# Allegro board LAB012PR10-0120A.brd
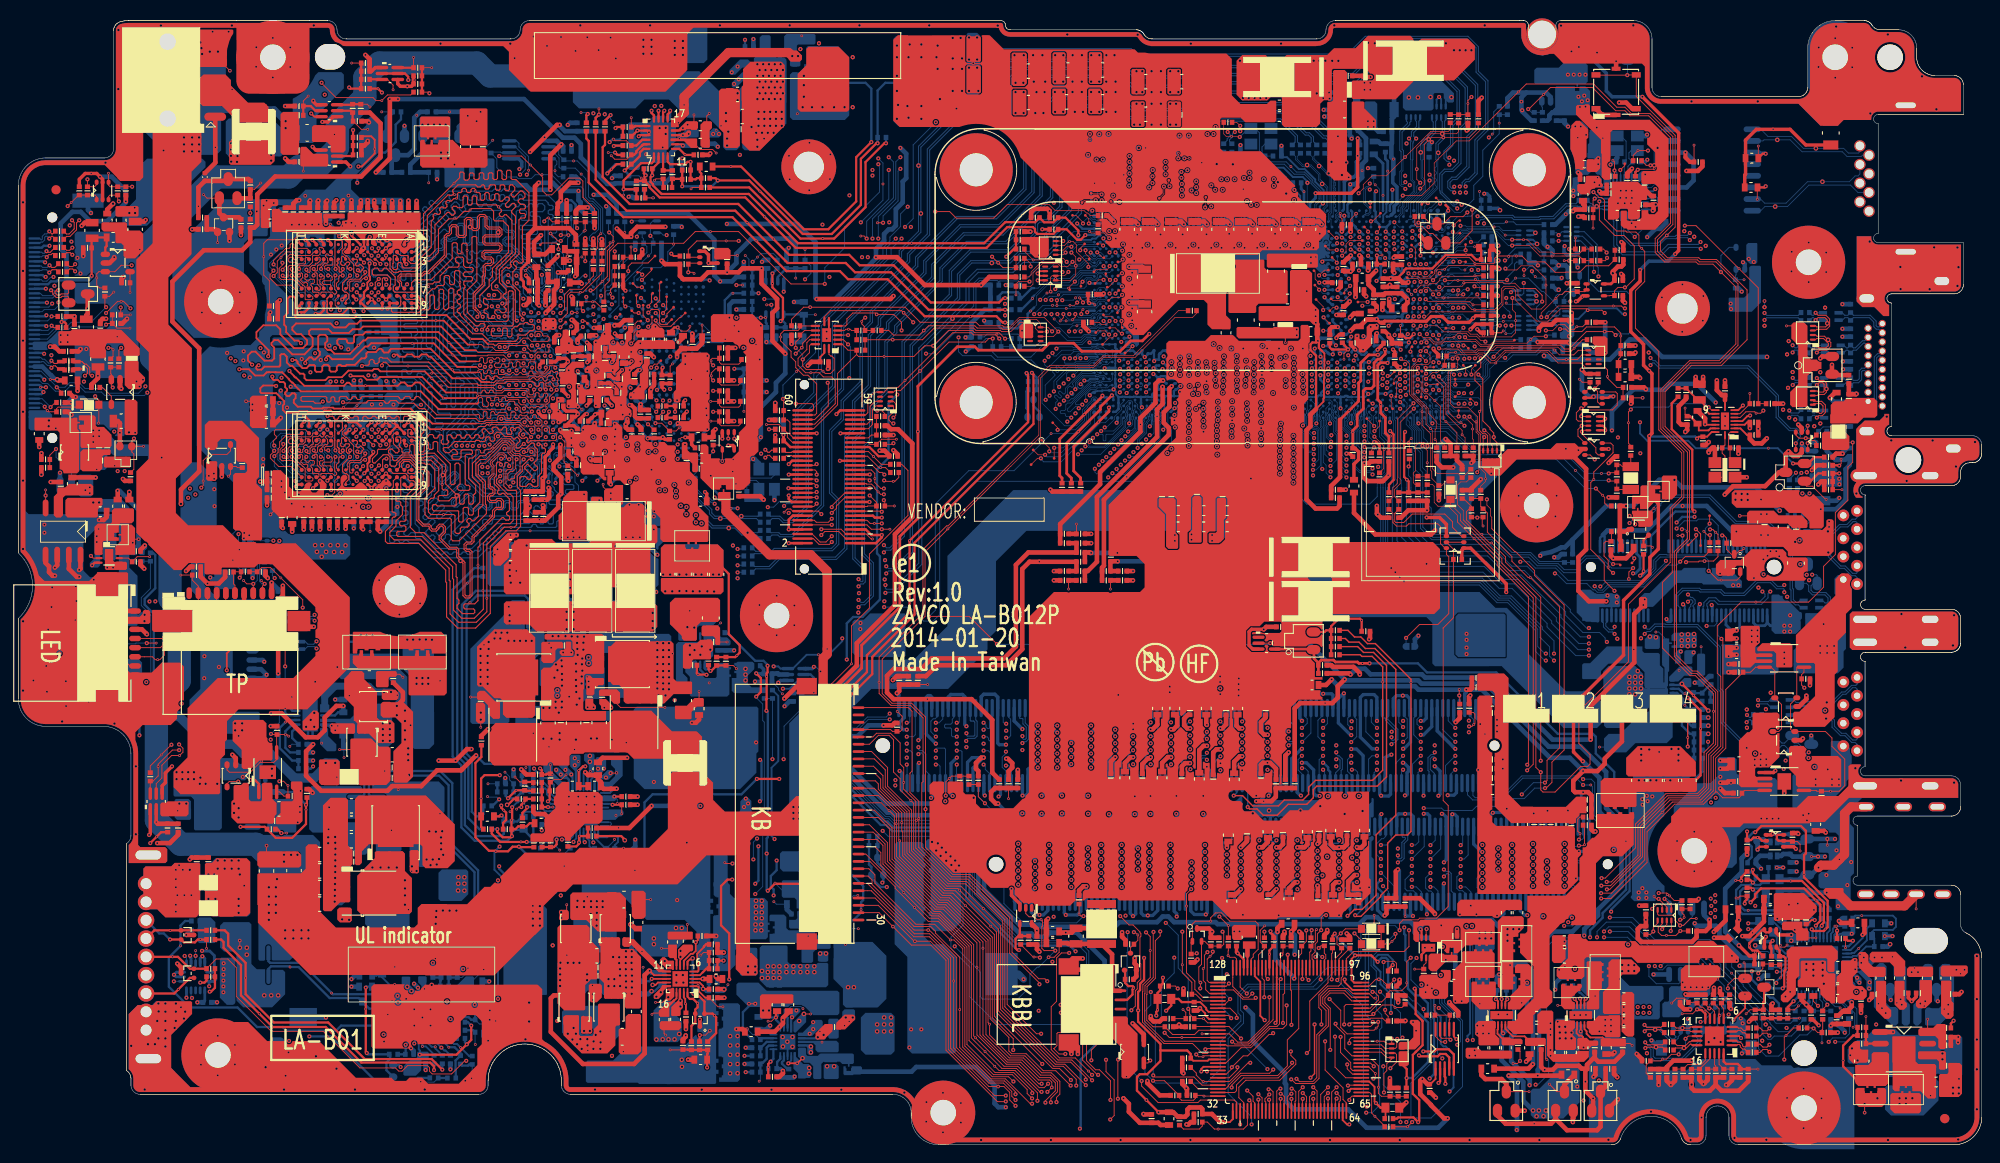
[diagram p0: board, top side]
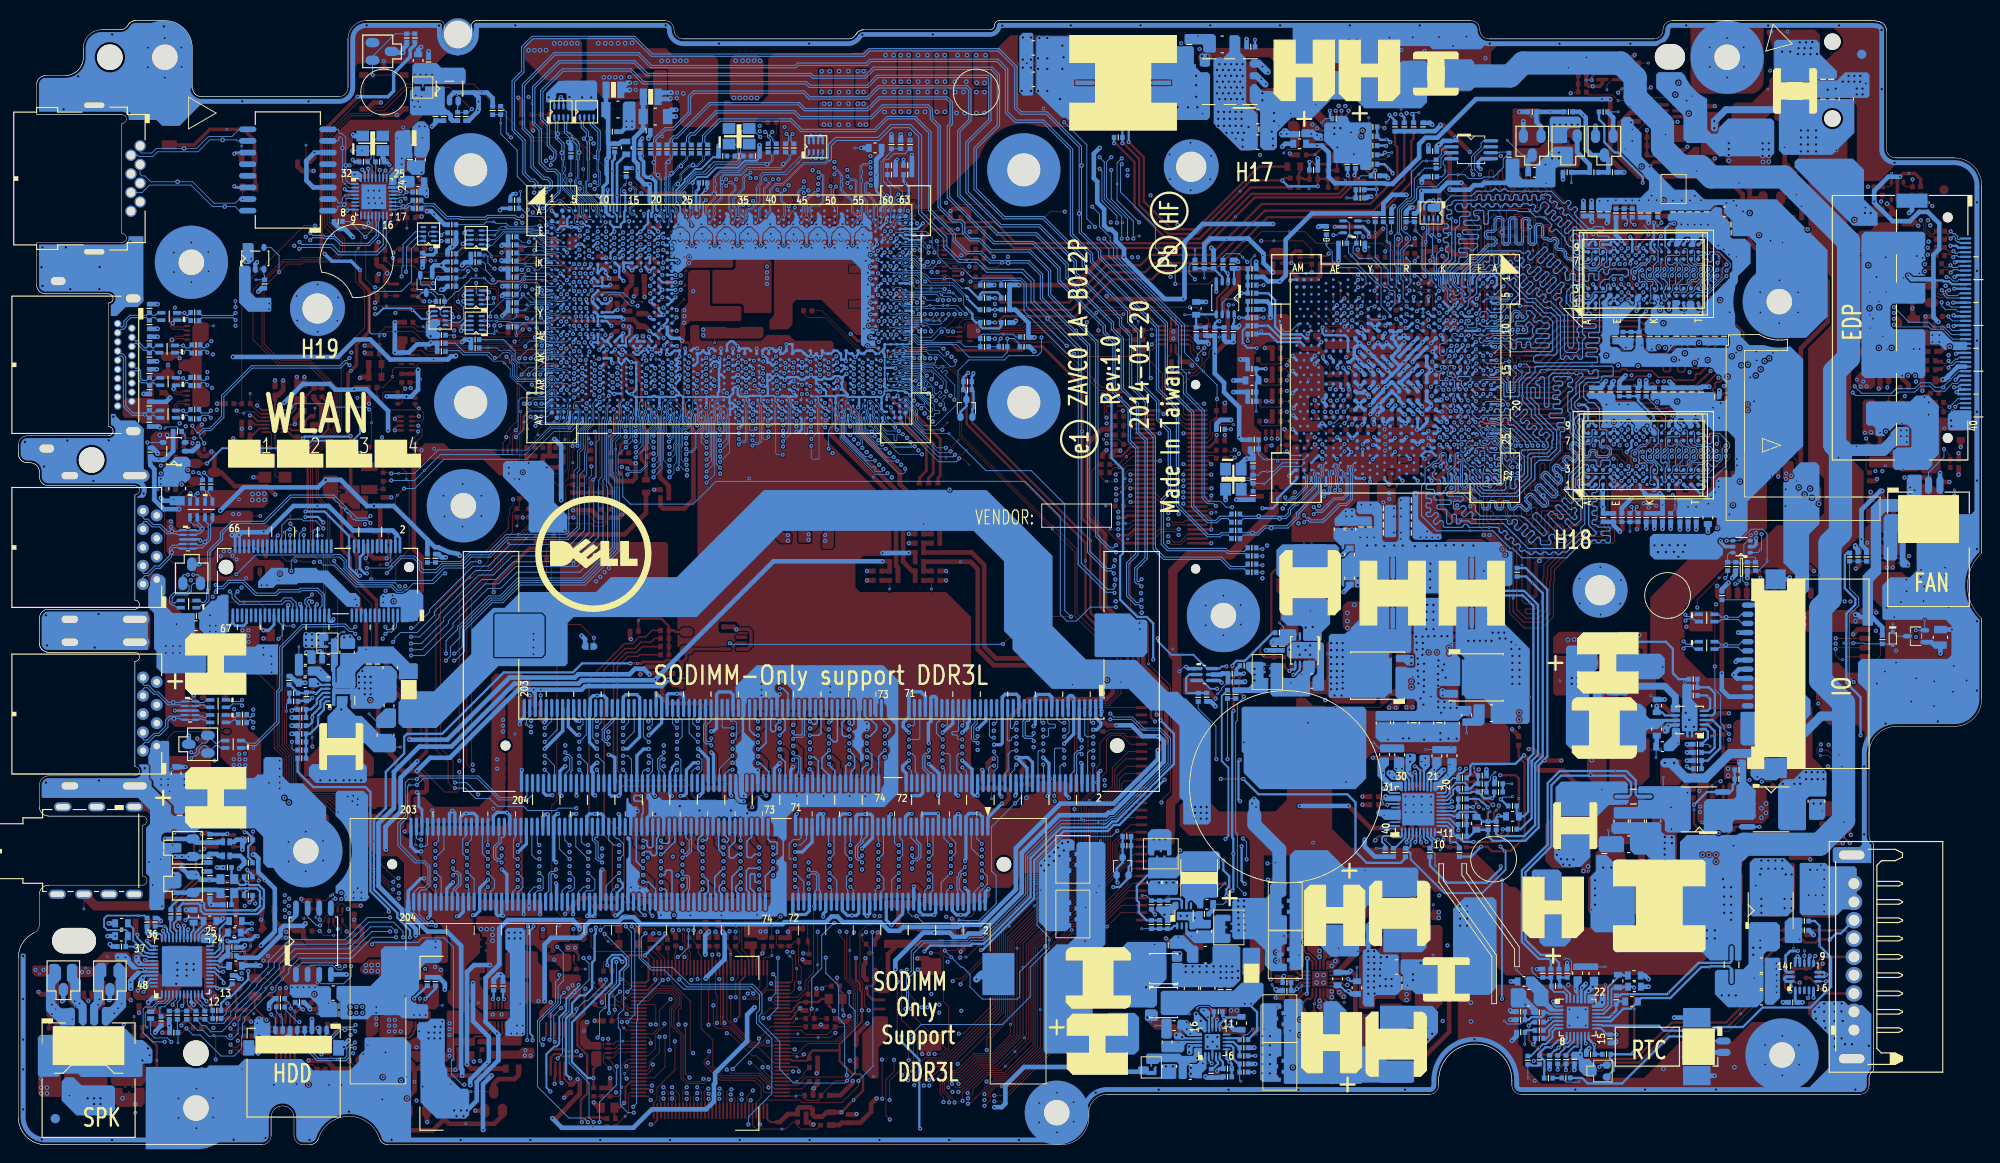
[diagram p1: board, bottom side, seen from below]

Outline 214.4 x 122.8 mm; copper layers: TOP, VCC, IN1, IN2, GND, BOTTOM. Coordinates in mm from the lower left corner of the outline.

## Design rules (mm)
net group CLK: nets CLKOUT_LPC0 XTAL24_IN
net group CLK-LAN: nets CLK_PCIE_LAN CLK_PCIE_LAN#
net group CLK-VGA: nets CLK_PEG_VGA CLK_PEG_VGA#
net group CLK-WLAN: nets CLK_PCIE_WLAN CLK_PCIE_WLAN#
net group DDRA-CTL: nets M_ODT0 M_ODT1
net group DDRB-CTL: nets M_ODT2 M_ODT3
net group EDP_AUX_C: nets EDP_AUX#_C EDP_AUX_C
net group EDP_TX0_C: nets EDP_TX0#_C EDP_TX0_C
net group EDP_TX1_C: nets EDP_TX1#_C EDP_TX1_C
net group I2C: nets I2C0_SCL I2C0_SDA
net group MG_DDRADQS2CLK_(CLK_DDR#1) - (DDRA-DQS1) [-1503MIL-2502MIL]: nets DDR_A_DQS1 DDR_A_DQS#1
net group MG_DDRADQS2CLK_(CLK_DDR#1) - (DDRA-DQS5) [-1503MIL-2502MIL]: nets DDR_A_DQS5 DDR_A_DQS#5
net group MG_DDRADQS2CLK_(CLK_DDR#1) - (DDRA-DQS7) [-1503MIL-2502MIL]: nets DDR_A_DQS7 DDR_A_DQS#7
net group MG_DDRBDQS2CLK_(CLK_DDR#3) - (DDRB-DQS1) [-1501MIL-2504MIL]: nets DDR_B_DQS1 DDR_B_DQS#1
net group MG_DDRBDQS2CLK_(CLK_DDR#3) - (DDRB-DQS4) [-1501MIL-2504MIL]: nets DDR_B_DQS4 DDR_B_DQS#4
net group PWR_60: nets +INV_PWR_SRC +LCDVDD
net group SATA_PRX_DTX_0: nets SATA_PRX_DTX_N0 SATA_PRX_DTX_P0
net group SATA_PRX_DTX_0_C: nets SATA_PRX_DTX_N0_C SATA_PRX_DTX_P0_C
net group SATA_PRX_DTX_0_R: nets SATA_PRX_DTX_N0_R SATA_PRX_DTX_P0_R
net group SATA_PRX_DTX_0_RC: nets SATA_PRX_DTX_N0_RC SATA_PRX_DTX_P0_RC
net group SATA_PTX_DRX_0: nets SATA_PTX_DRX_N0 SATA_PTX_DRX_P0
net group SATA_PTX_DRX_0_R: nets SATA_PTX_DRX_N0_R SATA_PTX_DRX_P0_R
net group SATA_PTX_DRX_0_RC: nets SATA_PTX_DRX_N0_RC SATA_PTX_DRX_P0_RC
net group SVID: nets H_CPU_SVIDALRT# PECI_EC
net group USB2-CAMERA: nets USB20_CAM_N7_R USB20_CAM_P7_R
net group USB2-TOUCH: nets USB20_TOUCH_N5 USB20_TOUCH_P5
net group USB2_JUSB1: nets USB20_JUSB2_N1_R USB20_JUSB2_P1_R
net group USB20_CR_6_R: nets USB20_CR_N6_R USB20_CR_P6_R
net group USB20_JUSB3_2_R: nets USB20_JUSB3_N2_R USB20_JUSB3_P2_R
net group ASYNCHRONOUS SIGNALS: nets H_CPU_SVIDCLK H_CPU_SVIDDATA H_THERMTRIP# PECI_KB9012 VR_SVID_ALRT# VR_SVID_CLK VR_SVID_DAT
net group CLK-33: nets CLK_BIASREF
net group CLK-DIFF: nets CLK_CPU_ITP CLK_CPU_ITP# CLK_XDP CLK_XDP#
net group CLK-SINGLE: nets CLK_PCI_LPC
net group CPU: nets H_CATERR# H_PROCHOT#_R XDP_OBS0_R XDP_OBS1_R XDP_RST#_R
net group CRITICAL: nets DSWODVREN H_CPUPWRGD H_VCCST_PWRGD_XDP INTRUDER# PCH_DPWROK PCH_INTVRMEN PM_APWROK_R SYS_PWROK
net group EDP: nets EDP_AUX EDP_AUX# EDP_TX0 EDP_TX0# EDP_TX1 EDP_TX1#
net group HDA: nets AUD_HP_OUT_L_CN AUD_HP_OUT_R_CN HPOUT-L HPOUT-R LINE-IN-L LINE-IN-R MIC_IN MIC_IN_R RING2 RING2_R
net group HDA-AUDIO: nets ME_EN N71037 PCH_AZ_BITCLK PCH_AZ_CODEC_BITCLK PCH_AZ_CODEC_RST# PCH_AZ_CODEC_SDIN0 PCH_AZ_CODEC_SDOUT PCH_AZ_CODEC_SYNC PCH_AZ_RST# PCH_AZ_SDOUT PCH_AZ_SYNC SUSACK#
net group HDMI-DATA: nets DDI1_LANE_N0 DDI1_LANE_N3 DDI1_LANE_P0 DDI1_LANE_P3 TMDS_L_TX0N TMDS_L_TX0P TMDS_L_TX1N TMDS_L_TX1P TMDS_L_TX2N TMDS_L_TX2P TMDS_L_TXCN TMDS_L_TXCP TMDS_TX0N TMDS_TX0P TMDS_TX1N TMDS_TX1P TMDS_TX2N TMDS_TX2P TMDS_TXCN TMDS_TXCP
net group HDMI-DDC: nets CPU_DPB_AUX CPU_DPB_AUX# CPU_DPB_CTRLCLK CPU_DPB_CTRLCLK_R CPU_DPB_CTRLDAT CPU_DPB_CTRLDAT_R CPU_DPC_AUX CPU_DPC_AUX# CPU_DPC_CTRLCLK CPU_DPC_CTRLDAT
net group MDI: nets MDI0+ MDI0- MDI1+ MDI1- MDO0+ MDO0- MDO1+ MDO1-
net group MG_DDRA-CTRL [0-104MIL]: nets DDR_CKE0_DIMMA DDR_CKE1_DIMMA DDR_CS0_DIMMA# DDR_CS1_DIMMA#
net group MG_DDRA_CMD [0-107MIL]: nets DDR_A_BS0 DDR_A_BS1 DDR_A_BS2 DDR_A_CAS# DDR_A_MA0 DDR_A_MA1 DDR_A_MA2 DDR_A_MA3 DDR_A_MA4 DDR_A_MA5 DDR_A_MA6 DDR_A_MA7 DDR_A_MA8 DDR_A_MA9 DDR_A_MA10 DDR_A_MA11 DDR_A_MA12 DDR_A_MA13 DDR_A_MA14 DDR_A_MA15 DDR_A_RAS# DDR_A_WE#
net group MG_DDRA_M_CLK_DDR0-1 [0-52MIL]: nets M_CLK_DDR0
net group MG_DDRACMD2CLK_(CLK_DDR#0) - (DDRA-CMD) [-502-499MIL]: nets M_CLK_DDR#0
net group MG_DDRACTL2CLK_(CLK_DDR#1) - (DDRA-CTL) [2-102MIL]: nets M_CLK_DDR#1
net group MG_DDRADQS2CLK_(CLK_DDR1) - (DDRA-DQS2) [-1503MIL-2502MIL]: nets M_CLK_DDR1
net group MG_DDRADQS2CLK_(CLK_DDR#1) - (DDRA-DQS0) [-1503MIL-2502MIL]: nets DDR_A_DQS0
net group MG_DDRADQS2CLK_(CLK_DDR#1) - (DDRA-DQS2) [-1503MIL-2502MIL]: nets DDR_A_DQS2
net group MG_DDRADQS2CLK_(CLK_DDR#1) - (DDRA-DQS3) [-1503MIL-2502MIL]: nets DDR_A_DQS3
net group MG_DDRADQS2CLK_(CLK_DDR#1) - (DDRA-DQS4) [-1503MIL-2502MIL]: nets DDR_A_DQS4
net group MG_DDRADQS2CLK_(CLK_DDR#1) - (DDRA-DQS6) [-1503MIL-2502MIL]: nets DDR_A_DQS6
net group MG_DDRADQS2DQ_(DDRA-DQ0-7) - (DDRA-DQS#0) [-28 - 18MIL]: nets DDR_A_D0 DDR_A_D1 DDR_A_D2 DDR_A_D3 DDR_A_D4 DDR_A_D5 DDR_A_D6 DDR_A_D7 DDR_A_DQS#0
net group MG_DDRADQS2DQ_(DDRA-DQ8-15) - (DDRA-DQS#1) [-28 - 18MIL]: nets DDR_A_D8 DDR_A_D9 DDR_A_D10 DDR_A_D11 DDR_A_D12 DDR_A_D13 DDR_A_D14 DDR_A_D15
net group MG_DDRADQS2DQ_(DDRA-DQ16-23) - (DDRA-DQS#2) [-28 - 18MIL]: nets DDR_A_D16 DDR_A_D17 DDR_A_D18 DDR_A_D19 DDR_A_D20 DDR_A_D21 DDR_A_D22 DDR_A_D23 DDR_A_DQS#2
net group MG_DDRADQS2DQ_(DDRA-DQ24-31) - (DDRA-DQS#3) [-28 - 18MIL]: nets DDR_A_D24 DDR_A_D25 DDR_A_D26 DDR_A_D27 DDR_A_D28 DDR_A_D29 DDR_A_D30 DDR_A_D31 DDR_A_DQS#3
net group MG_DDRADQS2DQ_(DDRA-DQ32-39) - (DDRA-DQS#4) [-28 - 18MIL]: nets DDR_A_D32 DDR_A_D33 DDR_A_D34 DDR_A_D35 DDR_A_D36 DDR_A_D37 DDR_A_D38 DDR_A_D39 DDR_A_DQS#4
net group MG_DDRADQS2DQ_(DDRA-DQ40-47) - (DDRA-DQS#5) [-28 - 18MIL]: nets DDR_A_D40 DDR_A_D41 DDR_A_D42 DDR_A_D43 DDR_A_D44 DDR_A_D45 DDR_A_D46 DDR_A_D47
net group MG_DDRADQS2DQ_(DDRA-DQ48-55) - (DDRA-DQS#6) [-28 - 18MIL]: nets DDR_A_D48 DDR_A_D49 DDR_A_D50 DDR_A_D51 DDR_A_D52 DDR_A_D53 DDR_A_D54 DDR_A_D55 DDR_A_DQS#6
net group MG_DDRADQS2DQ_(DDRA-DQ56-63) - (DDRA-DQS#7) [-28 - 18MIL]: nets DDR_A_D56 DDR_A_D57 DDR_A_D58 DDR_A_D59 DDR_A_D60 DDR_A_D61 DDR_A_D62 DDR_A_D63
net group MG_DDRB-CTRL [0-103MIL]: nets DDR_CKE2_DIMMB DDR_CKE3_DIMMB DDR_CS2_DIMMB# DDR_CS3_DIMMB#
net group MG_DDRB_CMD [0-103MIL]: nets DDR_B_BS0 DDR_B_BS1 DDR_B_BS2 DDR_B_CAS# DDR_B_MA0 DDR_B_MA1 DDR_B_MA2 DDR_B_MA3 DDR_B_MA4 DDR_B_MA5 DDR_B_MA6 DDR_B_MA7 DDR_B_MA8 DDR_B_MA9 DDR_B_MA10 DDR_B_MA11 DDR_B_MA12 DDR_B_MA13 DDR_B_MA14 DDR_B_MA15 DDR_B_RAS# DDR_B_WE#
net group MG_DDRB_M_CLK_DDR2-3 [0-68MIL]: nets M_CLK_DDR2
net group MG_DDRBDQS2CLK_(CLK_DDR3) - (DDRB-DQS6) [-1501MIL-2504MIL]: nets M_CLK_DDR3
net group MG_DDRBDQS2CLK_(CLK_DDR#2) - (DDRB-DQS0) [-1501MIL-2504MIL]: nets M_CLK_DDR#2
net group MG_DDRBDQS2CLK_(CLK_DDR#3) - (DDRB-DQS0) [-1501MIL-2504MIL]: nets DDR_B_DQS0
net group MG_DDRBDQS2CLK_(CLK_DDR#3) - (DDRB-DQS2) [-1501MIL-2504MIL]: nets DDR_B_DQS2
net group MG_DDRBDQS2CLK_(CLK_DDR#3) - (DDRB-DQS3) [-1501MIL-2504MIL]: nets DDR_B_DQS3
net group MG_DDRBDQS2CLK_(CLK_DDR#3) - (DDRB-DQS5) [-1501MIL-2504MIL]: nets DDR_B_DQS5
net group MG_DDRBDQS2CLK_(CLK_DDR#3) - (DDRB-DQS6) [-1501MIL-2504MIL]: nets DDR_B_DQS6 DDR_B_DQS#6 M_CLK_DDR#3
net group MG_DDRBDQS2CLK_(CLK_DDR#3) - (DDRB-DQS7) [-1501MIL-2504MIL]: nets DDR_B_DQS7
net group MG_DDRBDQS2DQ_(DDRB-DQ0-7) - (DDRB-DQS#0) [-25MIL-20MIL]: nets DDR_B_D0 DDR_B_D1 DDR_B_D2 DDR_B_D3 DDR_B_D4 DDR_B_D5 DDR_B_D6 DDR_B_D7 DDR_B_DQS#0
net group MG_DDRBDQS2DQ_(DDRB-DQ8-15) - (DDRB-DQS#1) [-25MIL-20MIL]: nets DDR_B_D8 DDR_B_D9 DDR_B_D10 DDR_B_D11 DDR_B_D12 DDR_B_D13 DDR_B_D14 DDR_B_D15
net group MG_DDRBDQS2DQ_(DDRB-DQ16-23) - (DDRB-DQS#2) [-25MIL-20MIL]: nets DDR_B_D16 DDR_B_D17 DDR_B_D18 DDR_B_D19 DDR_B_D20 DDR_B_D21 DDR_B_D22 DDR_B_D23 DDR_B_DQS#2
net group MG_DDRBDQS2DQ_(DDRB-DQ24-31) - (DDRB-DQS#3) [-25MIL-20MIL]: nets DDR_B_D24 DDR_B_D25 DDR_B_D26 DDR_B_D27 DDR_B_D28 DDR_B_D29 DDR_B_D30 DDR_B_D31 DDR_B_DQS#3
net group MG_DDRBDQS2DQ_(DDRB-DQ32-39) - (DDRB-DQS#4) [-25MIL-20MIL]: nets DDR_B_D32 DDR_B_D33 DDR_B_D34 DDR_B_D35 DDR_B_D36 DDR_B_D37 DDR_B_D38 DDR_B_D39
net group MG_DDRBDQS2DQ_(DDRB-DQ40-47) - (DDRB-DQS#5) [-25MIL-20MIL]: nets DDR_B_D40 DDR_B_D41 DDR_B_D42 DDR_B_D43 DDR_B_D44 DDR_B_D45 DDR_B_D46 DDR_B_D47 DDR_B_DQS#5
net group MG_DDRBDQS2DQ_(DDRB-DQ48-55) - (DDRB-DQS#6) [-25MIL-20MIL]: nets DDR_B_D48 DDR_B_D49 DDR_B_D50 DDR_B_D51 DDR_B_D52 DDR_B_D53 DDR_B_D54 DDR_B_D55
net group MG_DDRBDQS2DQ_(DDRB-DQ56-63) - (DDRB-DQS#7) [-25MIL-20MIL]: nets DDR_B_D56 DDR_B_D57 DDR_B_D58 DDR_B_D59 DDR_B_D60 DDR_B_D61 DDR_B_D62 DDR_B_D63 DDR_B_DQS#7
net group MG_GPU_DATA0-7_DQS0 [+-30MIL]: nets M_DA0 M_DA1 M_DA2 M_DA3 M_DA4 M_DA5 M_DA6 M_DA7 M_DQM0 M_DQS0
net group MG_GPU_DATA0-7_DQS#0 [+-30MIL]: nets M_DQS#0
net group MG_GPU_DATA8-15_DQS1 [+-30MIL]: nets M_DA8 M_DA9 M_DA10 M_DA11 M_DA12 M_DA13 M_DA14 M_DA15 M_DQM1 M_DQS1
net group MG_GPU_DATA8-15_DQS#1 [+-30MIL]: nets M_DQS#1
net group MG_GPU_DATA16-23_DQS2 [+-30MIL]: nets M_DA16 M_DA17 M_DA18 M_DA19 M_DA20 M_DA21 M_DA22 M_DA23 M_DQM2 M_DQS2
net group MG_GPU_DATA16-23_DQS#2 [+-30MIL]: nets M_DQS#2
net group MG_GPU_DATA24-31_DQS3 [+-30MIL]: nets M_DA24 M_DA25 M_DA26 M_DA27 M_DA28 M_DA29 M_DA30 M_DA31 M_DQM3 M_DQS3
net group MG_GPU_DATA24-31_DQS#3 [+-30MIL]: nets M_DQS#3
net group MG_GPU_DATA32-39_DQS4 [+-30MIL]: nets M_DA32 M_DA33 M_DA34 M_DA35 M_DA36 M_DA37 M_DA38 M_DA39 M_DQM4 M_DQS4
net group MG_GPU_DATA32-39_DQS#4 [+-30MIL]: nets M_DQS#4
net group MG_GPU_DATA40-47_DQS5 [+-30MIL]: nets M_DA40 M_DA41 M_DA42 M_DA43 M_DA44 M_DA45 M_DA46 M_DA47 M_DQM5 M_DQS5
net group MG_GPU_DATA40-47_DQS#5 [+-30MIL]: nets M_DQS#5
net group MG_GPU_DATA48-55_DQS6 [+-30MIL]: nets M_DA48 M_DA49 M_DA50 M_DA51 M_DA52 M_DA53 M_DA54 M_DA55 M_DQM6 M_DQS6
net group MG_GPU_DATA48-55_DQS#6 [+-30MIL]: nets M_DQS#6
net group MG_GPU_DATA56-63_DQS7 [+-30MIL]: nets M_DA56 M_DA57 M_DA58 M_DA59 M_DA60 M_DA61 M_DA62 M_DA63 M_DQM7 M_DQS7
net group MG_GPU_DATA56-63_DQS#7 [+-30MIL]: nets M_DQS#7
net group PCIE-GPU: nets PCIE_CRX_C_GTX_N0 PCIE_CRX_C_GTX_N1 PCIE_CRX_C_GTX_N2 PCIE_CRX_C_GTX_N3 PCIE_CRX_C_GTX_P0 PCIE_CRX_C_GTX_P1 PCIE_CRX_C_GTX_P2 PCIE_CRX_C_GTX_P3 PEG_CRX_GTX_N0 PEG_CRX_GTX_N1 PEG_CRX_GTX_N2 PEG_CRX_GTX_N3 PEG_CRX_GTX_P0 PEG_CRX_GTX_P1 PEG_CRX_GTX_P2 PEG_CRX_GTX_P3 PEG_CTX_GRX_C_N0 PEG_CTX_GRX_C_N1 PEG_CTX_GRX_C_N2 PEG_CTX_GRX_C_N3 PEG_CTX_GRX_C_P0 PEG_CTX_GRX_C_P1 PEG_CTX_GRX_C_P2 PEG_CTX_GRX_C_P3 PEG_CTX_GRX_N0 PEG_CTX_GRX_N1 PEG_CTX_GRX_N2 PEG_CTX_GRX_N3 PEG_CTX_GRX_P0 PEG_CTX_GRX_P1 PEG_CTX_GRX_P2 PEG_CTX_GRX_P3
net group PCIE-LAN: nets PCIE_PRX_LANTX_N3 PCIE_PRX_LANTX_N3_C PCIE_PRX_LANTX_P3 PCIE_PRX_LANTX_P3_C PCIE_PTX_LANRX_N3 PCIE_PTX_LANRX_N3_C PCIE_PTX_LANRX_P3 PCIE_PTX_LANRX_P3_C
net group PCIE-NGFF: nets PCIE_PRX_WLANTX_N4 PCIE_PRX_WLANTX_P4 PCIE_PTX_WLANRX_N4 PCIE_PTX_WLANRX_N4_C PCIE_PTX_WLANRX_P4 PCIE_PTX_WLANRX_P4_C
net group PCIE_COMP: nets PCH_OPI_COMP
net group PWR_10: nets +5V_USB_PWR1
net group PWR_20: nets +0.675VS +1.5VS +1.05VS_AUSB3PLL +3VS_CAM +5VS +5VS_KBL +RTCVCC +VCCIO_OUT
net group PWR_40: nets +VDISPLAY_VCC
net group PWR_75: nets +1.05VS
net group PWR_80: nets +5V_USB_PWR2
net group PWR_100: nets +VGA_PCIE
net group PWR_120: nets +3VS_WLAN_NGFF
net group PWR_135: nets +1.35V
net group RTC: nets PCH_RTCRST# PCH_RTCX1 PCH_RTCX2 SRTCRST#
net group SENSE: nets VCCSENSE
net group SMBUS: nets MEM_SMBCLK MEM_SMBDATA SML1_SMBCLK SML1_SMBDATA
net group SPI: nets PCH_SPI_CLK PCH_SPI_CLK_R PCH_SPI_CS0# PCH_SPI_HOLD1# PCH_SPI_HOLD# PCH_SPI_MISO PCH_SPI_MISO_1 PCH_SPI_MOSI PCH_SPI_MOSI_1 PCH_SPI_WP1# PCH_SPI_WP#
net group SPK: nets INT-SPK-L- INT-SPK-R+ INT-SPK-R- SPK_L1-_CONN SPK_L2+_CONN SPK_R1-_CONN SPK_R2+_CONN
net group USB2_JUSB0: nets USB20_JUSB1_N0 USB20_JUSB1_N0_R USB20_JUSB1_P0 USB20_JUSB1_P0_R
net group USB3-JUSB1: nets USB3RN2_JUSB2 USB3RN2_JUSB2_R USB3RP2_JUSB2 USB3RP2_JUSB2_R USB3TN2_JUSB2 USB3TN2_JUSB2_C USB3TN2_JUSB2_R USB3TP2_JUSB2 USB3TP2_JUSB2_C USB3TP2_JUSB2_R
net group USB3-JUSB2: nets USB3RN1_JUSB1 USB3RN1_JUSB1_R USB3RP1_JUSB1 USB3RP1_JUSB1_R USB3TN1_JUSB1_C USB3TN1_JUSB1_R USB3TP1_JUSB1_C USB3TP1_JUSB1_R
nets with their own width: min track width 0.254; nets N63469524 N63469526 REMOTE2+ REMOTE2-

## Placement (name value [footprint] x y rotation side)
C35  2.2U_0402_6.3V6M  [C_0402]  131.5 71.25 270 top
C36  2.2U_0402_6.3V6M  [C_0402]  128.71 71.51 270 top
C37  2.2U_0402_6.3V6M  [C_0402]  125.91 71.25 270 top
C38  2.2U_0402_6.3V6M  [C_0402]  124.9 71.25 270 top
C39  10U_0603_6.3V6M  [C_0603]  132.71 67.49 180 top
C40  22U_0603_6.3V6M  [C_0603]  131.88 89.4 270 top
C41  10U_0603_6.3V6M  [C_0603]  132.71 69.27 180 top
C42  10U_0603_6.3V6M  [C_0603]  130.17 67.49 180 top
C43  22U_0603_6.3V6M  [C_0603]  141.85 88.83 180 top
C44  22U_0603_6.3V6M  [C_0603]  146.04 94.67 0 top
C45  10U_0603_6.3V6M  [C_0603]  127.37 67.49 180 top
C46  22U_0603_6.3V6M  [C_0603]  138.42 112.32 180 top
C47  22U_0603_6.3V6M  [C_0603]  138.42 113.59 180 top
C50  1U_0402_6.3V6K  [C_0402]  149.03 94.62 270 top
C51  1U_0402_6.3V6K  [C_0402]  145.73 76.08 270 top
C52  0.1U_0402_10V7K  [C_0402]  150.93 88.4 270 top
C53  1U_0402_6.3V6K  [C_0402]  150.55 94.62 270 top
C54  1U_0402_6.3V6K  [C_0402]  152.84 71.25 270 top
C55  0.1U_0402_10V7K  [C_0402]  153.85 71.25 270 top
C56  0.1U_0402_10V7K  [C_0402]  151.82 71.25 270 top
C57  1U_0402_6.3V6K  [C_0402]  151.06 96.12 90 top
C58  1U_0402_6.3V6K  [C_0402]  146.31 110.8 180 bottom
C59  100U_1206_6.3V6M  [C_1206]  146.17 112.32 180 bottom
C60  10U_0603_6.3V6M  [C_0603]  139.31 92.38 180 top
C61  1U_0402_6.3V6K  [C_0402]  147.35 87.81 0 top
C62  1U_0402_6.3V6K  [C_0402]  146.44 87.56 180 top
C63  1U_0402_6.3V6K  [C_0402]  149.99 110.67 180 bottom
C64  1U_0402_6.3V6K  [C_0402]  143.21 87.56 90 top
C65  100U_1206_6.3V6M  [C_1206]  150.23 113.09 180 bottom
C66  22U_0603_6.3V6M  [C_0603]  159.51 97.97 0 top
C67  1U_0402_6.3V6K  [C_0402]  159.75 96.7 0 top
C68  0.1U_0402_10V7K  [C_0402]  149.03 89.79 270 top
C69  1U_0402_6.3V6K  [C_0402]  144.71 90.66 90 top
C70  100U_1206_6.3V6M  [C_1206]  134.04 88.76 90 top
C71  0.1U_0402_10V7K  [C_0402]  149.03 92.84 270 top
C72  10U_0603_6.3V6M  [C_0603]  130.17 69.27 180 top
C73  1U_0402_6.3V6K  [C_0402]  148.01 92.84 270 top
C74  10U_0603_6.3V6M  [C_0603]  127.37 69.27 180 top
C75  0.1U_0402_10V7K  [C_0402]  147.63 91.06 270 top
C76  1U_0402_6.3V6K  [C_0402]  146.03 93.4 0 top
C77  0.1U_0402_10V7K  [C_0402]  149.08 87.56 0 top
C78  22U_0603_6.3V6M  [C_0603]  146.49 89.4 90 top
C79  220P_0402_50V8J  [C_0402]  119.06 108.82 90 bottom
C80  0.1U_0402_10V7K  [C_0402]  117.91 101.5 0 top
C81  1U_0402_6.3V6K  [C_0402]  150.3 86.24 270 top
C82  22U_0603_6.3V6M  [C_0603]  151.38 91.37 180 top
C83  1U_0402_6.3V6K  [C_0402]  144.71 96.4 270 top
C84  100U_1206_6.3V6M  [C_1206]  137.34 96.77 270 top
C85  1U_0402_6.3V6K  [C_0402]  144.76 116.77 0 top
C86  100U_1206_6.3V6M  [C_1206]  143.5 113.09 0 top
C87  1U_0402_6.3V6K  [C_0402]  146.61 96.19 180 top
C88  1U_0402_6.3V6K  [C_0402]  144.41 94.16 180 top
C89  1U_0402_6.3V6K  [C_0402]  157.11 22.79 180 top
C90  1U_0402_6.3V6K  [C_0402]  174.99 87.3 0 top
C91  1U_0402_6.3V6K  [C_0402]  144.28 71.56 180 top
C92  1U_0402_6.3V6K  [C_0402]  147.43 96.19 0 top
C93  1U_0402_6.3V6K  [C_0402]  175.24 81.59 0 top
C2305  10U_0603_6.3V6M  [C_0603]  169.6 10.79 270 top
C2306  10U_0603_6.3V6M  [C_0603]  168.33 10.79 270 top
C2307  10U_0805_10V4Z  [C_0805]  169.69 20.63 180 top
C2308  10U_0603_6.3V6M  [C_0603]  169.54 22.28 180 top
C2309  0.01U_0603_25V7K  [C_0603]  170.87 11.29 270 top
C2310  10U_0805_10V4Z  [C_0805]  157.37 17.07 180 top
C2311  10U_0603_6.3V6M  [C_0603]  161.22 11.29 270 top
C2312  10U_0603_6.3V6M  [C_0603]  157.47 18.6 180 top
C2313  10U_0603_6.3V6M  [C_0603]  159.95 11.29 270 top
C2314  0.01U_0603_25V7K  [C_0603]  162.49 11.29 270 top
C2315  10U_0603_6.3V6M  [C_0603]  165.09 14.03 0 top
C2316  10U_0603_6.3V6M  [C_0603]  174.62 12.25 0 top
C2317  10U_0603_6.3V6M  [C_0603]  165.09 12.63 0 top
C2318  10U_0603_6.3V6M  [C_0603]  174.62 13.52 0 top
C2322  0.01U_0603_25V7K  [C_0603]  173.41 11.29 270 top
C2323  10U_0603_6.3V6M  [C_0603]  174.62 14.79 0 top
C2324  10U_0603_6.3V6M  [C_0603]  174.62 16.06 0 top
C2325  0.01U_0603_25V7K  [C_0603]  165.03 11.29 270 top
C2326  68P_0402_50V8J  [C_0402]  182.56 25.76 90 top
C2327  0.1U_0402_10V7K  [C_0402]  177.73 25.2 90 top
C2328  10U_0603_6.3V6M  [C_0603]  162.49 24.63 90 top
C2329  10U_0603_6.3V6M  [C_0603]  163.76 24.63 90 top
C2498  0.1U_0402_10V6K  [C_0402]  154.11 6.61 270 top
C2500  2200P_0402_25V7K  [C_0402]  93.81 32.67 180 bottom
C2502  2200P_0402_25V7K  [C_0402]  93.81 33.68 180 bottom
C2504  2200P_0402_25V7K  [C_0402]  111.19 83.37 180 bottom
C2505  2200P_0402_25V7K  [C_0402]  111.19 82.48 180 bottom
C4311  0.1U_0402_16V7K  [C_0402]  4.04 98.91 0 top
C4312  0.1U_0402_16V7K  [C_0402]  4.04 99.8 0 top
C4313  0.1U_0402_16V7K  [C_0402]  4.04 97.13 0 top
C4314  0.1U_0402_16V7K  [C_0402]  4.04 98.02 0 top
C4321  0.1U_0402_16V7K  [C_0402]  4.37 96.24 0 top
C4322  0.1U_0402_16V7K  [C_0402]  4.37 95.36 0 top
C5212  68P_0402_50V8J  [C_0402]  107.07 89.82 180 bottom
C5213  0.1U_0402_10V6K  [C_0402]  154.62 19.18 270 top
C5214  2200P_0402_25V7K  [C_0402]  153.47 19.18 270 top
C5215  0.47U_0402_6.3V6K  [C_0402]  144.58 87.61 90 top
C5216  1000P_0402_50V7K  [C_0402]  168.84 17.38 90 bottom
C5217  1000P_0402_50V7K  [C_0402]  169.73 17.38 90 bottom
C5218  1000P_0402_50V7K  [C_0402]  161.47 16.87 90 bottom
C5219  1000P_0402_50V7K  [C_0402]  162.49 16.87 90 bottom
CA1  10U_0603_6.3V6M  [C_0603]  190.62 26.85 0 top
CA2  10U_0603_6.3V6M  [C_0603]  190.62 25.58 0 top
CA21  22P_0402_50V8J  [C_0402]  196.96 12.25 0 bottom
CA22  22P_0402_50V8J  [C_0402]  4.68 82.1 0 top
CA23  2.2U_0603_6.3V6K  [C_0603]  195.26 25.65 270 bottom
CA24  1U_0402_6.3V6K  [C_0402]  199.52 22.53 180 top
CA25  1U_0402_6.3V6K  [C_0402]  199.45 24.77 270 bottom
CA29  1000P_0402_50V7K  [C_0402]  203.33 16.44 180 top
CA30  1000P_0402_50V7K  [C_0402]  205.47 16.57 0 top
CA31  1000P_0402_50V7K  [C_0402]  208.16 16.57 180 top
CA32  1000P_0402_50V7K  [C_0402]  210.55 16.44 0 top
CA33  100P_0402_50V8J  [C_0402]  193.48 27.82 270 bottom
CA38  1000P_0402_50V7K  [C_0402]  193.48 33 90 bottom
CA39  100P_0402_50V8J  [C_0402]  193.48 28.93 90 bottom
CA40  1000P_0402_50V7K  [C_0402]  193.48 31.75 270 bottom
CA51  0.1U_0402_16V7K  [C_0402]  194.22 24.09 90 top
CA53  4.7U_0603_6.3V6K  [C_0603]  199.38 18.22 180 top
CA54  0.1U_0402_16V7K  [C_0402]  201.22 16.13 270 top
CA55  4.7U_0603_6.3V6K  [C_0603]  199.38 16.95 180 top
CA56  0.1U_0402_16V7K  [C_0402]  199.02 15.8 180 top
CA57  4.7U_0603_6.3V6K  [C_0603]  199.7 14.6 270 top
CA58  0.1U_0402_16V7K  [C_0402]  198.56 14.1 270 top
CA59  4.7U_0603_6.3V6K  [C_0603]  194.75 16.25 90 top
CA60  0.1U_0402_16V7K  [C_0402]  195.76 14.61 270 top
CA61  4.7U_0603_6.3V6K  [C_0603]  202.43 22.79 0 bottom
CA62  10U_0603_6.3V6M  [C_0603]  192.78 24.44 0 bottom
CA63  10U_0603_6.3V6M  [C_0603]  203.83 24.19 180 bottom
CA64  10U_0603_6.3V6M  [C_0603]  196.02 17.64 270 top
CA65  0.1U_0402_16V7K  [C_0402]  193.22 14.74 270 top
CA67  4.7U_0603_6.3V6K  [C_0603]  191.38 24.44 180 bottom
CA68  4.7U_0603_6.3V6K  [C_0603]  191.51 23.17 180 bottom
CA69  100P_0402_50V8J  [C_0402]  191.45 13.82 90 top
CA71  4.7U_0603_6.3V6K  [C_0603]  193.17 23.87 90 top
CA74  10U_0603_6.3V6M  [C_0603]  191.38 19.54 180 bottom
CC1  15P_0402_50V8J  [C_0402]  174.55 75.19 270 top
CC2  15P_0402_50V8J  [C_0402]  174.55 70.72 90 top
CC3  1U_0402_6.3V6K  [C_0402]  150.74 68.5 90 top
CC4  1U_0402_6.3V6K  [C_0402]  149.68 68.5 90 top
CC5  27P_0402_50V8J  [C_0402]  197.92 14.61 270 bottom
CC6  15P_0402_50V8J  [C_0402]  133.46 108.01 0 bottom
CC7  15P_0402_50V8J  [C_0402]  137.93 108.01 180 bottom
CC8  0.022U_0402_16V7K  [C_0402]  118.34 61.65 0 top
CC9  0.022U_0402_16V7K  [C_0402]  113.77 66.73 0 top
CC10  0.022U_0402_16V7K  [C_0402]  116.47 61.65 180 top
CC11  0.1U_0402_10V7K  [C_0402]  174.3 94.42 0 top
CC13  0.1U_0402_10V7K  [C_0402]  87.56 85.53 0 top
CC14  0.1U_0402_10V7K  [C_0402]  95.1 75.21 0 top
CC15  0.1U_0402_10V7K  [C_0402]  83.57 76.89 180 top
CC16  0.1U_0402_10V7K  [C_0402]  93.71 77.53 0 top
CC17  0.1U_0402_10V7K  [C_0402]  83.57 79.18 180 top
CC18  0.1U_0402_10V7K  [C_0402]  140.9 109.22 270 bottom
CC19  0.1U_0402_10V7K  [C_0402]  141.79 109.22 270 bottom
CC20  0.1U_0402_10V7K  [C_0402]  139.12 109.22 270 bottom
CC21  0.1U_0402_10V7K  [C_0402]  140.01 109.22 270 bottom
CC22  0.1U_0402_10V7K  [C_0402]  144.46 109.22 270 bottom
CC23  0.1U_0402_10V7K  [C_0402]  145.34 109.22 270 bottom
CC24  0.1U_0402_10V7K  [C_0402]  142.68 109.22 270 bottom
CC25  0.1U_0402_10V7K  [C_0402]  143.57 109.22 270 bottom
CC26  1U_0603_10V6K  [C_0603]  175 65.21 0 top
CC27  100P_0402_50V8J  [C_0402]  119.51 106.99 180 bottom
CC28  100P_0402_50V8J  [C_0402]  116.82 106.99 0 bottom
CC29  0.1U_0402_10V7K  [C_0402]  85.35 88.45 180 top
CC30  0.047U_0402_16V4Z  [C_0402]  82.66 78.16 0 bottom
CC31  0.047U_0402_16V4Z  [C_0402]  167.52 98.73 180 bottom
CC32  0.1U_0402_10V7K  [C_0402]  130.61 109.35 270 bottom
CC33  0.047U_0402_16V4Z  [C_0402]  170.24 93.2 90 top
CC34  0.047U_0402_16V4Z  [C_0402]  167.52 99.62 180 bottom
CC35  0.047U_0402_16V4Z  [C_0402]  147.76 75.57 270 top
CC36  0.1U_0402_10V7K  [C_0402]  132.52 109.35 270 bottom
CC37  47U_0603_2.5V7  [C_0603]  174.75 83.88 0 top
CC38  47U_0603_2.5V7  [C_0603]  174.75 85.27 0 top
CC40  0.1U_0402_10V7K  [C_0402]  129.72 109.35 270 bottom
CC41  0.1U_0402_10V7K  [C_0402]  131.63 109.35 270 bottom
CC42  22P_0402_50V8J  [C_0402]  108.95 99.75 0 top
CD1  2.2U_0402_6.3V6M  [C_0402]  97.21 50.27 90 top
CD2  0.1U_0402_10V7K  [C_0402]  96.2 50.27 90 top
CD3  0.1U_0402_10V7K  [C_0402]  104.83 39.35 90 top
CD4  1U_0402_6.3V6K  [C_0402]  119.31 39.6 90 top
CD5  1U_0402_6.3V6K  [C_0402]  122.74 39.6 90 top
CD6  1U_0402_6.3V6K  [C_0402]  127.06 39.6 90 top
CD7  1U_0402_6.3V6K  [C_0402]  130.49 39.48 90 top
CD8  1U_0402_6.3V6K  [C_0402]  135.69 39.6 90 top
CD9  1U_0402_6.3V6K  [C_0402]  136.2 47.88 270 top
CD10  1U_0402_6.3V6K  [C_0402]  127.95 47.88 270 top
CD11  1U_0402_6.3V6K  [C_0402]  131.88 47.88 270 top
CD12  10U_0603_6.3V6M  [C_0603]  124.39 48.38 270 top
CD13  10U_0603_6.3V6M  [C_0603]  126.29 48.38 270 top
CD14  10U_0603_6.3V6M  [C_0603]  129.72 48.38 270 top
CD15  330U_D3_2.5VY_R6M  [C_D3]  138.46 59.36 0 top
CD16  10U_0603_6.3V6M  [C_0603]  120.83 39.36 90 top
CD17  10U_0603_6.3V6M  [C_0603]  124.9 39.36 90 top
CD18  10U_0603_6.3V6M  [C_0603]  128.96 39.23 90 top
CD19  10U_0603_6.3V6M  [C_0603]  132.77 39.18 90 top
CD20  10U_0603_6.3V6M  [C_0603]  133.15 48.38 270 top
CD21  2.2U_0402_6.3V6M  [C_0402]  137.34 38.97 90 top
CD22  0.1U_0402_10V7K  [C_0402]  138.36 38.97 90 top
CD23  0.1U_0402_10V7K  [C_0402]  138.31 56.57 180 top
CD24  0.1U_0402_10V7K  [C_0402]  160.51 47.17 0 top
CD25  0.1U_0402_10V7K  [C_0402]  160.51 42.09 0 top
CD26  0.1U_0402_10V7K  [C_0402]  160.51 41.08 0 top
CD27  0.1U_0402_10V7K  [C_0402]  160.51 40.06 0 top
CD28  10U_0603_6.3V6M  [C_0603]  160.27 48.44 0 top
CD29  10U_0603_6.3V6M  [C_0603]  160.27 38.79 0 top
CD30  2.2U_0402_6.3V6M  [C_0402]  158.73 49.97 0 top
CD31  0.1U_0402_10V7K  [C_0402]  158.73 50.98 0 top
CD32  2.2U_0402_6.3V6M  [C_0402]  109.15 38.97 90 top
CD33  0.1U_0402_10V7K  [C_0402]  108.13 38.97 90 top
CD34  0.1U_0402_10V7K  [C_0402]  115.83 26.29 90 top
CD35  1U_0402_6.3V6K  [C_0402]  136.45 26.39 90 top
CD36  1U_0402_6.3V6K  [C_0402]  141.92 26.27 90 top
CD37  1U_0402_6.3V6K  [C_0402]  145.22 26.39 90 top
CD38  1U_0402_6.3V6K  [C_0402]  146.36 26.39 90 top
CD39  1U_0402_6.3V6K  [C_0402]  134.17 34.42 270 top
CD40  1U_0402_6.3V6K  [C_0402]  138.11 34.55 270 top
CD41  1U_0402_6.3V6K  [C_0402]  142.04 34.68 270 top
CD42  1U_0402_6.3V6K  [C_0402]  145.09 34.68 270 top
CD43  10U_0603_6.3V6M  [C_0603]  136.45 34.92 270 top
CD44  10U_0603_6.3V6M  [C_0603]  132.14 34.54 270 top
CD45  10U_0603_6.3V6M  [C_0603]  140.77 34.92 270 top
CD46  10U_0603_6.3V6M  [C_0603]  132.52 25.9 90 top
CD47  10U_0603_6.3V6M  [C_0603]  147 35.04 270 top
CD48  10U_0603_6.3V6M  [C_0603]  143.31 35.04 270 top
CD49  10U_0603_6.3V6M  [C_0603]  138.74 26.15 90 top
CD50  10U_0603_6.3V6M  [C_0603]  143.57 25.9 90 top
CD51  330U_D3_2.5VY_R6M  [C_D3]  138.46 64.19 0 top
CD52  2.2U_0402_6.3V6M  [C_0402]  150.42 26.01 90 top
CD53  0.1U_0402_10V7K  [C_0402]  149.41 26.01 90 top
CD54  0.1U_0402_10V7K  [C_0402]  167.32 34.52 90 top
CD55  0.1U_0402_10V7K  [C_0402]  166.43 34.52 90 top
CD56  0.1U_0402_10V7K  [C_0402]  165.54 34.52 90 top
CD57  0.1U_0402_10V7K  [C_0402]  169.6 34.4 90 top
CD58  10U_0603_6.3V6M  [C_0603]  168.46 34.28 90 top
CD59  10U_0603_6.3V6M  [C_0603]  164.27 34.28 90 top
CD60  2.2U_0402_6.3V6M  [C_0402]  171.79 37.7 180 top
CD61  0.1U_0402_10V7K  [C_0402]  171.79 36.68 180 top
CD62  22U_0603_6.3V6M  [C_0603]  141.98 50.22 180 top
CD63  330U_D3_2.5VY_R6M  [C_D3]  148.75 118.42 0 top
CD64  0.1U_0402_10V7K  [C_0402]  146.69 56.09 0 top
CD65  330U_D3_2.5VY_R6M  [C_D3]  140.67 116.64 180 top
CE1  0.1U_0402_10V7K  [C_0402]  129.29 3.36 180 top
CE2  0.1U_0402_10V7K  [C_0402]  128.02 9.45 180 top
CE5  1000P_0402_50V7K  [C_0402]  133.03 22.61 270 top
CE6  1000P_0402_50V7K  [C_0402]  128.4 14.66 90 top
CE7  0.1U_0402_10V7K  [C_0402]  124.69 17.33 0 top
CE8  0.1U_0402_10V7K  [C_0402]  149.79 5.29 90 top
CE9  100P_0402_50V8J  [C_0402]  149.21 2.85 0 top
CE11  0.1U_0402_10V7K  [C_0402]  129.29 2.47 180 top
CE12  0.1U_0402_10V7K  [C_0402]  126.12 13.77 180 top
CE15  0.1U_0402_10V7K  [C_0402]  111.23 22.76 270 top
CE16  4.7U_0805_10V4Z  [C_0805]  134.42 21.81 90 top
CE18  100P_0402_50V8J  [C_0402]  140.14 22.61 270 top
CE19  47P_0402_50V8J  [C_0402]  110.34 22.79 270 top
CE20  0.1U_0402_16V7K  [C_0402]  171.99 121.37 270 bottom
CE22  2.2U_0603_6.3V6K  [C_0603]  5.9 71.49 90 top
CE23  1000P_0402_50V7K  [C_0402]  4.63 71.48 90 top
CE24  0.01U_0402_16V7K  [C_0402]  3.44 74.86 180 top
CE25  2.2U_0603_6.3V6K  [C_0603]  8.25 69.14 0 top
CE26  0.1U_0402_10V7K  [C_0402]  149.59 17.33 0 top
CE27  0.1U_0402_10V7K  [C_0402]  128.15 16.44 180 top
CE28  0.1U_0402_10V7K  [C_0402]  125.2 12.88 0 top
CE29  220P_0402_50V8J  [C_0402]  128.02 8.44 180 top
CE30  0.1U_0402_10V7K  [C_0402]  138.11 21.7 90 top
CE31  1000P_0402_50V7K  [C_0402]  128.53 5.39 180 top
CE32  1000P_0402_50V7K  [C_0402]  149.59 13.52 0 top
CE34  0.1U_0402_10V7K  [C_0402]  130.23 21.7 90 top
CE35  220P_0402_50V8J  [C_0402]  128.07 20.83 270 top
CE36  0.047U_0402_16V4Z  [C_0402]  128.4 12.88 180 top
CE56  1U_0603_10V6K  [C_0603]  113.66 23.3 180 top
CE57  10U_0603_6.3V6M  [C_0603]  113.66 22.03 180 top
CE58  1U_0402_6.3V6K~D  [C_0402]  19.91 63.13 180 top
CE59  0.1U_0402_10V6K  [C_0402]  12.43 64.83 0 top
CE60  2200P_0402_25V7K  [C_0402]  12.43 63.68 0 top
CE61  1U_0402_6.3V6K  [C_0402]  123.75 3.31 270 top
CG2  0.1U_0402_10V7K  [C_0402]  189.08 78.92 0 top
CG3  0.1U_0402_10V7K  [C_0402]  186.37 81.89 90 top
CG4  0.1U_0402_10V7K  [C_0402]  183.95 77.35 270 top
CG5  22U_0805_6.3V6M  [C_0805]  183.57 81.37 90 top
CG6  2.2U_0603_6.3V6K  [C_0603]  183.37 78.77 90 top
CG7  5P_0402_50V8C  [C_0402]  190.86 80.95 0 top
CG8  15P_0402_50V8J  [C_0402]  186.92 76.13 0 top
CG9  12P_0402_50V8J  [C_0402]  186.06 76.13 180 top
CG10  0.1U_0402_10V7K  [C_0402]  189.08 77.53 0 top
CI1  220U_6.3V_M  [C_MP6VLPS220MC4R2]  195.64 52.51 0 bottom
CI2  0.1U_0402_16V7K  [C_0402]  195.42 57.77 180 bottom
CI3  0.1U_0402_10V7K  [C_0402]  194.29 71.71 90 bottom
CI4  0.1U_0402_10V7K  [C_0402]  193.4 71.71 90 bottom
CI6  4.7U_0805_10V4Z  [C_0805]  188.74 41.58 180 top
CI7  0.1U_0402_16V7K  [C_0402]  188.22 39.68 180 top
CI8  220U_6.3V_M  [C_MP6VLPS220MC4R2]  195.64 37.9 0 bottom
CI9  0.1U_0402_16V7K  [C_0402]  196.78 36.45 270 bottom
CI10  0.1U_0402_10V7K  [C_0402]  190.38 46.99 180 bottom
CI11  0.1U_0402_10V7K  [C_0402]  190.38 46.11 180 bottom
CI12  4.7U_0805_10V4Z  [C_0805]  188.49 53.9 180 top
CI13  0.1U_0402_16V7K  [C_0402]  188.35 51.62 180 top
CI14  0.1U_0402_16V7K  [C_0402]  188.35 52.51 180 top
CI15  0.1U_0402_16V7K  [C_0402]  194.74 50.89 0 top
CI17  0.1U_0402_16V7K  [C_0402]  196.91 38.61 270 top
CI18  47U_0805_6.3V4Z  [C_0805]  188.49 55.68 180 top
CI26  0.1U_0402_16V7K  [C_0402]  188.22 38.41 180 top
CI40  10U_0603_6.3V6M  [C_0603]  195.7 56.7 180 bottom
CI43  10U_0603_6.3V6M  [C_0603]  197.16 39.87 90 bottom
CI44  4.7U_0805_10V4Z  [C_0805]  27.62 36.68 0 top
CI45  0.1U_0402_16V7K  [C_0402]  27.54 35.36 0 top
CI46  0.1U_0402_16V7K  [C_0402]  29.44 38.08 0 top
CI47  0.1U_0402_16V7K  [C_0402]  28.25 44.81 90 top
CL3  0.1U_0402_25V6  [C_0402]  171.63 108.08 270 bottom
CL4  4.7U_0603_6.3V6K  [C_0603]  170.49 108.32 270 bottom
CL5  0.1U_0402_25V6  [C_0402]  178.57 102.72 90 top
CL6  0.1U_0402_25V6  [C_0402]  177.68 102.67 180 top
CL7  0.1U_0402_25V6  [C_0402]  175.7 105.8 270 top
CL8  0.1U_0402_25V6  [C_0402]  173.46 104.83 0 top
CL9  1U_0402_6.3V4Z  [C_0402]  173.46 103.94 0 top
CL12  0.1U_0402_16V7K  [C_0402]  177.6 105.29 270 top
CL13  4.7U_0603_6.3V6K  [C_0603]  175.32 101.53 180 top
CL14  10U_0603_6.3V6M  [C_0603]  177.67 101.53 180 top
CL15  0.1U_0402_10V7K  [C_0402]  168.84 112.78 270 bottom
CL16  0.1U_0402_16V4Z  [C_0402]  170.54 105.47 0 top
CL17  4.7U_0603_6.3V6K  [C_0603]  170.87 104.51 270 top
CL19  0.1U_0402_10V7K  [C_0402]  167.95 112.78 270 bottom
CL30  0.1U_0402_10V7K  [C_0402]  170.41 102.29 0 bottom
CL31  0.1U_0402_10V7K  [C_0402]  170.41 103.18 0 bottom
CL33  10P_1206_2KV8J  [C_1206]  197.92 109.21 90 top
CL36  10P_0402_50V8J  [C_0402]  177.17 107.37 180 bottom
CL37  10P_0402_50V8J  [C_0402]  174.48 107.37 0 bottom
CL38  0.1U_0603_25V7K  [C_0603]  170.74 117.72 90 bottom
CL39  1U_0402_6.3V6K  [C_0402]  169.6 117.83 90 bottom
CL41  0.01U_0402_16V7K  [C_0402]  183.9 107.36 180 top
CM3  100U_1206_6.3V6M  [C_1206]  197.05 70.34 90 bottom
CM4  22U_0603_6.3V6M~D  [C_0603]  192.72 66.79 90 top
CM5  0.1U_0402_10V7K~D  [C_0402]  194.11 66.78 90 top
CM6  22U_0603_6.3V6M~D  [C_0603]  189.41 67.3 90 top
CM7  0.1U_0402_10V7K~D  [C_0402]  190.68 67.29 90 top
CM8  1U_0402_6.3V6K  [C_0402]  199.98 76.11 270 bottom
CMOS1  SHORT PADS~D  [SHORTPADS]  152.03 54.44 180 bottom
CS5  1000P_0402_50V7K  [C_0402]  179.84 15.17 180 bottom
CS6  0.1U_0402_25V6K  [C_0402]  179.84 14.28 180 bottom
CS7  10U_0805_10V6K  [C_0805]  180.87 16.57 180 bottom
CS27  0.1U_0402_25V6K  [C_0402]  180.02 8.26 270 top
CS30  0.01U_0402_16V7K  [C_0402]  180.75 10.34 180 top
CS31  0.01U_0402_16V7K  [C_0402]  180.65 12.25 180 top
CS32  0.01U_0402_16V7K  [C_0402]  180.75 11.23 180 top
CS33  0.01U_0402_16V7K  [C_0402]  189.79 11.87 180 top
CS34  0.01U_0402_16V7K  [C_0402]  180.65 13.14 180 top
CS35  0.01U_0402_16V7K  [C_0402]  189.79 12.76 180 top
CS36  0.01U_0402_16V7K  [C_0402]  189.79 10.98 180 top
CS37  0.01U_0402_16V7K  [C_0402]  189.79 10.09 180 top
CS42  0.01U_0402_16V7K  [C_0402]  179.13 8.26 270 top
CS43  0.1U_0402_16V4Z~D  [C_0402]  20.17 15.55 0 bottom
CS44  10U_0805_10V4Z~D  [C_0805]  4.5 54.58 90 bottom
CV1  0.1U_0402_10V7K  [C_0402]  81.92 68.89 180 bottom
CV2  0.1U_0402_10V7K  [C_0402]  81.92 68 180 bottom
CV3  0.1U_0402_10V7K  [C_0402]  81.92 67.11 180 bottom
CV4  0.1U_0402_10V7K  [C_0402]  81.92 66.22 180 bottom
CV5  0.1U_0402_10V7K  [C_0402]  80.14 62.54 180 bottom
CV6  0.1U_0402_10V7K  [C_0402]  80.14 63.43 180 bottom
CV7  0.1U_0402_10V7K  [C_0402]  80.14 64.32 180 bottom
CV8  0.1U_0402_10V7K  [C_0402]  80.14 65.21 180 bottom
CV9  1000P_0402_50V7K  [C_0402]  59.57 107.6 270 bottom
CV10  0.1U_0402_16V4Z  [C_0402]  59.49 108.54 0 bottom
CV11  0.68U_0402_10V  [C_0402]  76.56 85.91 0 top
CV15  0.68U_0402_10V  [C_0402]  76.56 80.07 0 top
CV17  8.2P_0402_50V8D  [C_0402]  79.56 74.02 90 bottom
CV18  8.2P_0402_50V8D  [C_0402]  79.56 71.38 270 bottom
CV19  10U_0603_6.3V6M  [C_0603]  78.99 83.49 0 bottom
CV20  1U_0402_6.3V4Z  [C_0402]  79.23 81.21 0 bottom
CV21  0.1U_0402_10V6K  [C_0402]  79.23 82.22 0 bottom
CV22  10U_0603_6.3V6M  [C_0603]  48.82 108.32 90 top
CV23  0.1U_0402_10V7K  [C_0402]  50.73 108.56 90 top
CV24  0.1U_0402_10V7K  [C_0402]  44.81 106.23 0 bottom
CV25  0.1U_0402_10V7K  [C_0402]  48.62 112.83 0 bottom
CV26  1U_0402_6.3V4Z  [C_0402]  73.62 86.97 90 top
CV27  10U_0603_6.3V6M  [C_0603]  72.57 86.97 90 top
CV28  0.68U_0402_10V  [C_0402]  76.56 82.35 0 top
CV29  0.68U_0402_10V  [C_0402]  76.56 83.49 0 top
CV33  1U_0402_6.3V4Z  [C_0402]  71.18 84.08 270 top
CV34  0.1U_0402_10V6K  [C_0402]  70.29 84.08 270 top
CV38  10U_0603_6.3V6M  [C_0603]  75.32 75 180 top
CV39  0.1U_0402_10V6K  [C_0402]  74.81 73.84 180 top
CV40  2.2U_0402_6.3V6M  [C_0402]  59.01 86.82 270 top
CV41  2.2U_0402_6.3V6M  [C_0402]  58.6 80.7 0 top
CV42  2.2U_0402_6.3V6M  [C_0402]  57.26 85.53 0 top
CV43  10U_0603_6.3V6M  [C_0603]  27.81 78.8 180 top
CV44  10U_0603_6.3V6M  [C_0603]  27.81 80.07 180 top
CV45  10U_0603_6.3V6M  [C_0603]  27.81 81.34 180 top
CV46  1U_0402_6.3V4Z  [C_0402]  78.67 71.76 270 top
CV47  2.2U_0402_6.3V6M  [C_0402]  59.54 79.51 0 top
CV48  2.2U_0402_6.3V6M  [C_0402]  32.44 88.78 270 bottom
CV49  0.1U_0402_10V6K  [C_0402]  59.44 87.69 180 top
CV50  0.1U_0402_10V6K  [C_0402]  59.72 88.7 0 top
CV51  0.1U_0402_10V6K  [C_0402]  60.61 86.97 270 top
CV52  0.1U_0402_10V6K  [C_0402]  61.47 87 0 top
CV53  0.1U_0402_10V6K  [C_0402]  58.43 79.53 180 top
CV54  10U_0603_6.3V6M  [C_0603]  64.57 74.79 270 top
CV55  10U_0603_6.3V6M  [C_0603]  63.3 76.19 270 top
CV56  1U_0402_6.3V4Z  [C_0402]  72.98 74.3 90 top
CV57  1U_0402_6.3V4Z  [C_0402]  61.04 77.27 90 top
CV58  1U_0402_6.3V4Z  [C_0402]  61.02 75.75 180 top
CV59  1U_0402_6.3V4Z  [C_0402]  61.86 74.22 180 top
CV60  1U_0402_6.3V4Z  [C_0402]  59.77 77.63 90 top
CV61  10U_0603_6.3V6M  [C_0603]  73.53 77.27 0 top
CV62  1U_0402_6.3V4Z  [C_0402]  67.93 80.27 270 top
CV63  0.1U_0402_10V6K  [C_0402]  68.81 80.27 270 top
CV64  1U_0402_6.3V4Z  [C_0402]  68.51 83.27 0 top
CV65  1U_0402_6.3V4Z  [C_0402]  68.13 81.72 0 top
CV66  0.1U_0402_10V6K  [C_0402]  68.51 84.15 0 top
CV67  10U_0603_6.3V6M  [C_0603]  66.15 86.78 270 top
CV68  10U_0603_6.3V6M  [C_0603]  70.01 87.3 90 top
CV69  10U_0603_6.3V6M  [C_0603]  68.74 87.3 90 top
CV70  10U_0603_6.3V6M  [C_0603]  65.07 79.86 180 top
CV71  1U_0402_6.3V4Z  [C_0402]  63.2 87 0 top
CV72  1U_0402_6.3V4Z  [C_0402]  63.58 84.03 0 top
CV73  1U_0402_6.3V4Z  [C_0402]  62.41 82.22 270 top
CV74  1U_0402_6.3V4Z  [C_0402]  63.23 86.14 180 top
CV75  1U_0402_6.3V4Z  [C_0402]  64.47 82.27 90 top
CV76  1U_0402_6.3V4Z  [C_0402]  66.25 82.15 180 top
CV77  1U_0402_6.3V4Z  [C_0402]  64.09 85.22 90 top
CV78  1U_0402_6.3V4Z  [C_0402]  66.43 83.7 180 top
CV79  1U_0402_6.3V4Z  [C_0402]  63.33 81.36 0 top
CV80  1U_0402_6.3V4Z  [C_0402]  64.55 78.82 180 top
CV81  10U_0603_6.3V6M  [C_0603]  59.68 97.85 180 top
CV82  1U_0402_6.3V4Z  [C_0402]  60.97 95.51 180 top
CV83  10U_0603_6.3V6M  [C_0603]  60.97 96.55 180 top
CV84  10U_0603_6.3V6M  [C_0603]  56.57 95.88 90 top
CV85  1U_0402_6.3V4Z  [C_0402]  56.7 94.16 180 top
CV86  0.1U_0402_10V6K  [C_0402]  56.7 92.38 180 top
CV87  1U_0402_6.3V4Z  [C_0402]  61.47 85.22 90 top
CV88  10U_0603_6.3V6M  [C_0603]  60.42 83.67 0 top
CV89  1U_0402_6.3V4Z  [C_0402]  59.44 83.37 270 top
CV90  1U_0402_6.3V4Z  [C_0402]  59.37 84.18 90 top
CV91  10U_0603_6.3V6M  [C_0603]  58.82 94.19 0 top
CV92  1U_0402_6.3V4Z  [C_0402]  58.5 92.38 180 top
CV93  0.1U_0402_10V6K  [C_0402]  57.84 94.24 270 top
CV94  1U_0402_6.3V4Z  [C_0402]  56.44 68.18 90 top
CV95  1U_0402_6.3V4Z  [C_0402]  57.21 71.38 270 top
CV96  120P_0402_50V8J  [C_0402]  66.91 96.96 0 top
CV97  68P_0402_50V8J  [C_0402]  65.13 93.91 0 top
CV98  0.1U_0402_16V4Z  [C_0402]  63.73 96.52 270 top
CV99  0.1U_0402_16V4Z  [C_0402]  62.79 96.52 270 top
CV100  0.1U_0402_10V6K  [C_0402]  34.85 68.97 270 bottom
CV101  0.1U_0402_10V6K  [C_0402]  38.54 81.77 90 bottom
CV102  0.01U_0402_16V7K  [C_0402]  39.3 68.05 90 bottom
CV103  10U_0603_6.3V6M  [C_0603]  29.9 69.21 270 bottom
CV104  1U_0402_6.3V4Z  [C_0402]  31.17 68.97 270 bottom
CV105  1U_0402_6.3V4Z  [C_0402]  32.06 68.97 270 bottom
CV106  1U_0402_6.3V4Z  [C_0402]  40.19 68.97 270 bottom
CV107  1U_0402_6.3V4Z  [C_0402]  41.33 68.97 270 bottom
CV108  1U_0402_6.3V4Z  [C_0402]  29.6 81.72 180 bottom
CV109  1U_0402_6.3V4Z  [C_0402]  30.66 81.77 90 bottom
CV110  1U_0402_6.3V4Z  [C_0402]  31.68 81.77 90 bottom
CV111  0.1U_0402_10V6K  [C_0402]  32.7 81.77 90 bottom
CV112  0.1U_0402_10V6K  [C_0402]  41.59 81.77 90 bottom
CV113  0.1U_0402_10V6K  [C_0402]  42.6 81.77 90 bottom
CV114  0.1U_0402_10V6K  [C_0402]  33.71 81.77 90 bottom
CV115  0.1U_0402_10V6K  [C_0402]  40.57 81.77 90 bottom
CV116  0.1U_0402_10V6K  [C_0402]  34.73 81.77 90 bottom
CV117  0.1U_0402_10V6K  [C_0402]  35.74 81.77 90 bottom
CV118  10U_0603_6.3V6M  [C_0603]  29.9 69.21 270 top
CV119  1U_0402_6.3V4Z  [C_0402]  28.07 71.56 180 top
CV120  1U_0402_6.3V4Z  [C_0402]  31.17 68.97 270 top
CV121  1U_0402_6.3V4Z  [C_0402]  35.74 68.97 270 top
CV122  1U_0402_6.3V4Z  [C_0402]  40.19 68.97 270 top
CV123  1U_0402_6.3V4Z  [C_0402]  28.07 72.45 180 top
CV124  1U_0402_6.3V4Z  [C_0402]  38.41 68.97 270 top
CV125  1U_0402_6.3V4Z  [C_0402]  36.63 68.97 270 top
CV126  0.1U_0402_10V6K  [C_0402]  28.07 70.67 180 top
CV127  0.1U_0402_10V6K  [C_0402]  32.95 68.97 270 top
CV128  0.1U_0402_10V6K  [C_0402]  39.3 68.97 270 top
CV129  0.1U_0402_10V6K  [C_0402]  32.06 68.97 270 top
CV130  0.1U_0402_10V6K  [C_0402]  28.76 68.97 270 top
CV131  0.1U_0402_10V6K  [C_0402]  34.85 68.97 270 top
CV132  0.1U_0402_10V6K  [C_0402]  37.52 68.97 270 top
CV133  0.1U_0402_10V6K  [C_0402]  39.17 88.78 270 bottom
CV134  0.1U_0402_10V6K  [C_0402]  33.58 101.45 90 top
CV135  0.01U_0402_16V7K  [C_0402]  39.93 102.24 270 bottom
CV136  10U_0603_6.3V6M  [C_0603]  28.82 101.91 180 bottom
CV137  1U_0402_6.3V4Z  [C_0402]  42.6 101.45 90 bottom
CV138  1U_0402_6.3V4Z  [C_0402]  41.71 101.45 90 bottom
CV139  1U_0402_6.3V4Z  [C_0402]  37.27 101.32 90 bottom
CV140  1U_0402_6.3V4Z  [C_0402]  36.38 101.32 90 bottom
CV141  1U_0402_6.3V4Z  [C_0402]  31.93 101.45 90 bottom
CV142  1U_0402_6.3V4Z  [C_0402]  31.04 101.45 90 bottom
CV143  1U_0402_6.3V4Z  [C_0402]  33.71 101.45 90 bottom
CV144  0.1U_0402_10V6K  [C_0402]  40.82 101.45 90 bottom
CV145  0.1U_0402_10V6K  [C_0402]  34.47 88.78 270 bottom
CV146  0.1U_0402_10V6K  [C_0402]  36.25 88.78 270 bottom
CV147  0.1U_0402_10V6K  [C_0402]  35.36 88.78 270 bottom
CV148  0.1U_0402_10V6K  [C_0402]  30.03 101.45 90 bottom
CV149  0.1U_0402_10V6K  [C_0402]  32.82 101.45 90 bottom
CV150  0.1U_0402_10V6K  [C_0402]  43.49 101.45 90 bottom
CV151  10U_0603_6.3V6M  [C_0603]  28.19 101.66 180 top
CV152  1U_0402_6.3V4Z  [C_0402]  32.7 101.45 90 top
CV153  1U_0402_6.3V4Z  [C_0402]  38.16 101.45 90 top
CV154  1U_0402_6.3V4Z  [C_0402]  39.05 101.45 90 top
CV155  1U_0402_6.3V4Z  [C_0402]  37.27 101.45 90 top
CV156  1U_0402_6.3V4Z  [C_0402]  36.38 101.45 90 top
CV157  1U_0402_6.3V4Z  [C_0402]  39.93 101.45 90 top
CV158  1U_0402_6.3V4Z  [C_0402]  42.6 101.45 90 top
CV159  0.1U_0402_10V6K  [C_0402]  30.92 101.45 90 top
CV160  0.1U_0402_10V6K  [C_0402]  27.41 90.23 0 top
CV161  0.1U_0402_10V6K  [C_0402]  41.71 101.45 90 top
CV162  0.1U_0402_10V6K  [C_0402]  40.82 101.45 90 top
CV163  0.1U_0402_10V6K  [C_0402]  30.03 101.45 90 top
CV164  0.1U_0402_10V6K  [C_0402]  29.14 101.45 90 top
CV165  0.1U_0402_10V6K  [C_0402]  31.81 101.45 90 top
CV166  0.1U_0402_10V7K  [C_0402]  81.84 96.65 270 bottom
CV167  0.1U_0402_10V7K  [C_0402]  85.78 88.37 90 bottom
CV168  1U_0402_6.3V4Z  [C_0402]  61.32 79.05 0 top
CV169  10U_0603_6.3V6M  [C_0603]  85.78 92.07 270 bottom
CV170  0.1U_0402_10V7K  [C_0402]  81.72 88.37 90 bottom
CV171  0.1U_0402_10V6K  [C_0402]  32.95 68.97 270 bottom
CV172  1U_0402_6.3V4Z  [C_0402]  33.33 88.78 270 bottom
CV173  0.1U_0402_10V6K  [C_0402]  33.97 68.97 270 top
CV174  0.01U_0402_16V7K  [C_0402]  40.06 88.78 270 bottom
CV175  0.01U_0402_16V7K  [C_0402]  31.55 88.78 270 bottom
CV176  0.01U_0402_16V7K  [C_0402]  28.12 88.78 270 bottom
CV177  0.01U_0402_16V7K  [C_0402]  29.14 88.78 270 bottom
CV178  0.01U_0402_16V7K  [C_0402]  30.16 88.78 270 bottom
CV179  1U_0402_6.3V4Z  [C_0402]  28.07 73.33 180 top
CV180  0.1U_0402_10V6K  [C_0402]  43.49 101.45 90 top
CV181  1U_0402_6.3V4Z  [C_0402]  27.95 100.51 180 top
CV182  0.1U_0402_10V6K  [C_0402]  27.82 100.51 180 bottom
CV183  1U_0402_6.3V4Z  [C_0402]  27.82 99.62 180 bottom
CVT90  0.1U_0402_10V7K  [C_0402]  60.89 101.73 270 top
CX1  0.1U_0402_10V7K  [C_0402]  4.93 86.67 0 top
CX2  0.1U_0402_10V7K  [C_0402]  6.13 88.7 90 top
CX3  10U_0805_10V6K  [C_0805]  7.42 88.49 90 top
CX4  1000P_0402_50V7K  [C_0402]  9.71 76.59 270 top
CX5  0.1U_0603_25V7K  [C_0603]  2.28 78.38 270 top
CX7  4.7U_0805_10V4Z  [C_0805]  12.08 79.05 180 top
CX8  4.7U_0805_10V4Z  [C_0805]  8.69 86.67 270 top
CX9  0.1U_0402_10V7K  [C_0402]  8.9 82.73 180 top
CX11  0.1U_0402_10V7K  [C_0402]  8.95 88.75 90 top
CX12  0.1U_0402_10V7K  [C_0402]  195.59 82.94 180 bottom
CX13  0.1U_0402_10V7K  [C_0402]  195.59 83.82 180 bottom
CX14  0.1U_0402_10V7K  [C_0402]  195.59 79.3 180 bottom
CX15  0.1U_0402_10V7K  [C_0402]  195.59 80.32 180 bottom
CX16  0.1U_0402_10V7K  [C_0402]  195.46 86.49 180 bottom
CX17  0.1U_0402_10V7K  [C_0402]  195.46 87.38 180 bottom
CX18  0.1U_0402_10V7K  [C_0402]  195.59 90.02 180 bottom
CX19  0.1U_0402_10V7K  [C_0402]  195.59 90.91 180 bottom
CX20  220P_0402_50V8J  [C_0402]  198.13 71.56 180 top
CX21  0.1U_0402_16V7K  [C_0402]  199.89 81.07 90 top
CX22  10U_0603_6.3V6M  [C_0603]  198.56 80.76 90 top
CX23  3.3P_0402_50V8C  [C_0402]  200.08 82.94 270 bottom
CX24  3.3P_0402_50V8C  [C_0402]  200.08 83.8 90 bottom
CX25  3.3P_0402_50V8C  [C_0402]  200.08 79.38 270 bottom
CX26  3.3P_0402_50V8C  [C_0402]  200.08 80.24 90 bottom
CX27  3.3P_0402_50V8C  [C_0402]  200.08 86.49 270 bottom
CX28  3.3P_0402_50V8C  [C_0402]  200.08 87.35 90 bottom
CX29  3.3P_0402_50V8C  [C_0402]  200.08 90.05 270 bottom
CX30  3.3P_0402_50V8C  [C_0402]  200.08 90.91 90 bottom
CX49  4.7U_0805_10V4Z  [C_0805]  8.06 99.03 90 top
CX50  0.1U_0402_10V7K  [C_0402]  8.01 97.97 180 top
CX51  4.7U_0805_10V4Z  [C_0805]  12.76 99.15 90 top
CX52  0.1U_0402_10V7K  [C_0402]  12.2 94.16 180 top
DA8  -  [BAT54C-7-F_SOT23-3]  190.65 17.2 90 top
DA10  AZ5125-02S.R7G_SOT23-3  [AZ5125-02SPR7G_SOT23-3]  197.44 28.5 270 bottom
DA12  AZ5123-02S SOT23  [AZ5125-02SPR7G_SOT23-3]  197.44 32.44 270 bottom
DA13  AZ5125-02S.R7G_SOT23-3  [AZ5125-02SPR7G_SOT23-3]  204.4 16.92 180 bottom
DA14  AZ5125-02S.R7G_SOT23-3  [AZ5125-02SPR7G_SOT23-3]  209.48 16.92 180 bottom
DC1  -  [BAT54CW_SOT323-3]  176.17 67.24 90 top
DE1  -  [L03ESDL5V0CG3-2_SOT-523-3]  128.71 23.62 0 top
DE2  -  [L03ESDL5V0CC3-2_SOT23-3]  173.64 119.44 90 bottom
DE3  -  [RB751V-40_SOD323-2]  148.82 23.58 180 top
DE4  -  [RB751V-40_SOD323-2]  148.82 21.91 180 top
DH1  -  [RB751V-40_SOD323-2]  156.39 70.49 90 top
DI1  IP4292CZ10-TBR_XSON10_2.5X1~D  [IP4292CZ10-TBR_XSON10_2P5X1]  196.42 67.13 270 bottom
DI2  -  [L30ESDL5V0C3-2_SOT23-3]  195.47 63.41 0 bottom
DI4  IP4292CZ10-TBR_XSON10_2.5X1~D  [IP4292CZ10-TBR_XSON10_2P5X1]  196.19 48.43 270 bottom
DI5  -  [L30ESDL5V0C3-2_SOT23-3]  195.79 43.74 270 bottom
DS1  SDM10U45-7_SOD523-2~D  [SDM10U45-7_SOD523-2]  9.71 56 270 bottom
DX1  -  [RB751V-40_SOD323-2]  6.65 80.84 0 top
DX2  -  [PESD5V0U2BT_SOT23-3]  7.58 92.94 90 top
FD1  FIDUCAL  [FIDUCIAL_C40M80]  210.37 2.85 180 bottom
FD2  FIDUCIAL  [FIDUCIAL_C40M80]  210.37 2.85 0 top
FD3  FIDUCAL  [FIDUCIAL_C40M80]  13.1 119.13 180 bottom
FD4  FIDUCIAL  [FIDUCIAL_C40M80]  4.12 104.32 0 top
FE1  0.75A_24V_1812L075-24DR~OK  [F_1812L075-24DR]  118.29 21.94 90 top
FX1  1.5A_6V_1206L150PR~D  [F_1206L150PR]  198.76 79.31 270 top
H1  -  [H_2P8N]  206.4 74.8 0 top
H2  -  [H_2P8]  198.4 118.8 0 top
H3  -  [H_2P8]  195.5 96.4 0 top
H4  -  [H_2P8]  183 32.1 90 top
H5  -  [H_2P8]  195 4 0 top
H6  -  [H_2P8]  101 3.5 0 top
H7  -  [H_2P8]  21.8 9.8 0 top
H8  -  [H_2P8]  82.8 57.8 0 top
H9  -  [H_2P8]  27.8 118.8 0 top
H10  -  [H_3P0]  166.4 121.3 0 top
H11  -  [H_2P8]  22.1 92.1 0 top
H12  -  [H_2P8]  165.8 69.8 0 top
H13  -  [H_3P6]  165 106.5 0 top
H14  -  [H_3P6]  165 81.1 0 top
H15  -  [H_3P6]  104.6 106.5 0 top
H16  -  [H_3P6]  104.6 81.1 0 top
H17  -  [H_3P3]  86.32 106.83 0 top
H18  -  [H_3P3]  41.67 60.57 0 top
H19  -  [H_3P3]  181.73 91.35 0 top
H20  -  [H_2P8N]  195 10 0 top
H21  -  [H_2P8N]  204.4 118.8 0 top
H22  -  [H_2P8X3P3N]  34.04 118.85 90 top
H23  -  [H_2P8X4P8N]  208.31 22.28 90 top
HE1  100K_0402_1%_TSM0B104F4251RZ  [R_0402]  13.51 63.75 90 bottom
J9  2MM  [JUMP_43X39]  77.02 72.14 270 top
J510  -  [JUMP_43X79]  169.6 18.26 270 top
J511  -  [JUMP_43X79]  173.83 18.85 180 top
J512  -  [JUMP_43X79]  163.08 18.09 0 top
J513  -  [JUMP_43X79]  159.95 18.39 270 top
J514  -  [JUMP_43X79]  45.14 110.21 270 top
J515  -  [JUMP_43X79]  164.18 22.03 180 top
J516  -  [JUMP_43X79]  159.95 22.07 270 top
J518  -  [JUMP_43X39]  156.52 21.59 270 top
J519  -  [JUMP_43X39]  10.39 66.63 0 top
J520  -  [JUMP_43X39]  7.27 78.89 180 top
JDIMM1  BELLW_80001-1021  [BELLW_80001-1021_204P]  96.15 47.7 180 bottom
JDIMM2  BELLW_80011-1021  [BELLW_80011-1021_204P]  108.52 34.74 0 bottom
JEDP  STARC_107K40-000001-G2  [STARC_107K40-000001-G2_40P]  1.76 99 270 bottom
JFAN  ACES_88231-03041  [ACES_88231-03041_3P]  7.05 72.04 180 bottom
JHDD  E&T_4260K-F10N-00L  [E-T_4260K-F10N-00L_10P]  180.73 12.52 180 bottom
JHDMI  CONCR_099ATAC19NBLCNF  [CONCR_099ATAC19NBLCNF_19P]  203.55 89.7 270 bottom
JHP  SINGA_2SJ3080-001111F  [SINGA_2SJ3080-001111F_6P]  201.74 36.91 90 bottom
JIO  ACES_51524-0160N-001  [ACES_51524-0160N-001_16P]  25.55 43.95 90 bottom
JKB  HB_A823020-SBHR21  [HB_A823020-SBHR21_30P]  91.75 47.75 270 top
JKBBL  ACES_50524-00401-P01  [ACES_50524-00401-P01_4P-T]  120.35 16.82 270 top
JLAN  J-L_TNBNRAC80015008  [SDAN_601028-008041_8P-T]  201.1 109.12 270 bottom
JLED  ACES_51524-0080N-001  [ACES_51524-0080N-001_8P]  12.75 58.3 270 top
JNGFF  LOTES_APCI0019-P009A  [LOTES_APCI0019-P009A_67P]  172.48 57.83 0 bottom
JP3  2MM  [JUMP_43X39]  170.24 115.04 90 bottom
JP12  -  [JUMP_43X39]  176.84 70.11 270 top
JP13  -  [JUMP_43X79]  184.33 19.44 90 top
JP14  -  [JUMP_43X39]  178.65 71.37 0 top
JRTC  ACES_50271-0020N-001  [ACES_50271-0020N-001_2P]  28.21 11.33 270 bottom
JSPK  ACES_50278-00401-001  [ACES_50278-00401-001_4P]  208.6 14.05 180 bottom
JTP  ACES_51524-0080N-001  [ACES_51524-0080N-001_8P]  20.66 60.26 0 top
JTP1  ACES_51524-0100N-001  [ACES_51524-0100N-001_10P]  18.66 60.26 0 top
JUSB1  TAITW_PUBAU6-09FLBS1NN4H0  [TAITW_PUBAU6-09FLBS1NN4H0_9P]  199.29 61.75 270 bottom
JUSB2  TAITW_PUBAU6-09FLBS1NN4H0  [TAITW_PUBAU6-09FLBS1NN4H0_9P]  199.29 43.55 270 bottom
JXDP1  SAMTE_BSH-030-01-L-D-A  [SAMTE_BSH-030-01-L-D-A_60P]  91.37 65.71 90 top
L1  2.2UH_LQM2MPN2R2NG0L_30%  [MURAT_LQM2MPN2R2NG0L_2P]  144.54 114.48 0 bottom
L2  2.2UH_LQM2MPN2R2NG0L_30%  [MURAT_LQM2MPN2R2NG0L_2P]  148.61 115.24 0 bottom
L3  2.2UH_LQM2MPN2R2NG0L_30%  [MURAT_LQM2MPN2R2NG0L_2P]  138.36 90.39 270 top
L4  2.2UH_LQM2MPN2R2NG0L_30%  [MURAT_LQM2MPN2R2NG0L_2P]  139.88 95.14 90 top
L5  2.2UH_LQM2MPN2R2NG0L_30%  [MURAT_LQM2MPN2R2NG0L_2P]  146.14 115.24 180 top
LA1  BLM15BB221SN1D_2P  [MURAT_BLM15BB221SN1D_2P]  199.95 14.53 270 bottom
LA3  NBQ160808T-800Y-N 0603  [R_0603]  210.5 18.91 270 top
LA4  NBQ160808T-800Y-N 0603  [R_0603]  208.46 18.91 270 top
LA5  NBQ160808T-800Y-N 0603  [R_0603]  205.42 18.91 270 top
LA6  NBQ160808T-800Y-N 0603  [R_0603]  203.38 18.91 270 top
LA7  BLM15PX330SN1D 0402  [MURAT_BLM15BD601SN1D_2P]  192.07 33.08 180 bottom
LA8  CHILISIN NBQ160808T-800Y-N 0603  [KC_FBMA-L10-160808-800LMT_2P]  192.32 29.01 180 bottom
LA9  CHILISIN NBQ160808T-800Y-N 0603  [KC_FBMA-L10-160808-800LMT_2P]  192.32 27.49 180 bottom
LA10  BLM15PX330SN1D 0402  [MURAT_BLM15BD601SN1D_2P]  192.07 31.55 180 bottom
LE1  FBMA-L11-160808-800LMT_0603  [KC_FBMA-L11-160808-800LMT_2P]  125.9 15.93 180 top
LE2  FBMA-L11-160808-800LMT_0603  [KC_FBMA-L11-160808-800LMT_2P]  150.79 4.04 180 top
LI1  DLW21SN670HQ2L_4P  [MURAT_DLW21SN670HQ2L_4P]  195.66 70.25 270 bottom
LI2  WCM-2012HS-900T_4P  [KC_WCM-2012HS-900T_4P]  194.96 58.66 0 bottom
LI3  DLW21SN670HQ2L_4P  [MURAT_DLW21SN670HQ2L_4P]  194 70.25 270 bottom
LI4  DLW21SN670HQ2L_4P  [MURAT_DLW21SN670HQ2L_4P]  191.74 48.59 0 bottom
LI5  WCM-2012HS-900T_4P  [KC_WCM-2012HS-900T_4P]  190.09 43.34 0 bottom
LI6  DLW21SN670HQ2L_4P  [MURAT_DLW21SN670HQ2L_4P]  191.74 46.94 0 bottom
LI7  WCM-2012HS-900T_4P  [KC_WCM-2012HS-900T_4P]  30.88 57.95 180 bottom
LI8  WCM-2012HS-900T_4P  [KC_WCM-2012HS-900T_4P]  30.88 54.95 180 bottom
LL1  2.2UH_LQM2MPN2R2NG0L_30%  [MURAT_LQM2MPN2R2NG0L_2P]  171.98 109.96 180 bottom
LV2  BLM15BD121SN1D_0402  [R_0402]  80.14 84.76 180 bottom
LV3  BLM15BD121SN1D_0402  [R_0402]  74.81 76.13 180 top
LV4  BLM15BD121SN1D_0402  [R_0402]  68.64 86.42 270 top
LV6  BLM15BB221SN1D_2P  [MURAT_BLM15BB221SN1D_2P]  60.89 98.35 270 top
LV7  BLM15BD121SN1D_0402  [R_0402]  55.81 93.27 0 top
LV8  BLM15BD121SN1D_0402  [R_0402]  57.84 96.02 270 top
LV25  BLM15BD121SN1D_0402  [R_0402]  60.64 82.17 0 top
LV26  BLM15BD121SN1D_0402  [R_0402]  60.64 81.31 0 top
LX1  FBMA-L11-201209-221LMA30T_0805  [KC_FBMA-L11-201209-221LMA30_2P]  12.38 85.08 90 top
LX2  WCM-2012HS-900T_4P  [KC_WCM-2012HS-900T_4P]  197.2 82.97 0 bottom
LX3  WCM-2012HS-900T_4P  [KC_WCM-2012HS-900T_4P]  197.2 79.41 0 bottom
LX4  WCM-2012HS-900T_4P  [KC_WCM-2012HS-900T_4P]  197.3 86.52 0 bottom
LX5  WCM-2012HS-900T_4P  [KC_WCM-2012HS-900T_4P]  197.07 90.08 0 bottom
LX6  WCM-2012HS-900T_4P  [KC_WCM-2012HS-900T_4P]  6.37 84.75 180 top
NOREF  -  []  12.26 1.07 0 top
NOREF#2  -  []  36.02 21.59 0 top
NOREF#3  -  []  140.19 76.72 0 top
NOREF#4  -  []  165 81.1 0 top
NOREF#5  -  []  41.67 60.57 0 top
NOREF#6  -  []  27.8 118.8 0 top
NOREF#7  -  []  195 4 0 top
NOREF#8  -  []  165.8 69.8 0 top
NOREF#9  -  []  22.1 92.1 0 top
NOREF#10  -  []  101 3.5 0 top
NOREF#11  -  []  104.6 106.5 0 top
NOREF#12  -  []  183 32.1 0 top
NOREF#13  -  []  86.32 106.83 0 top
NOREF#14  -  []  195.5 96.4 0 top
NOREF#15  -  []  181.73 91.35 0 top
NOREF#16  -  []  98.03 101.85 0 top
NOREF#17  -  []  82.8 57.8 0 top
NOREF#18  -  []  104.6 81.1 0 top
NOREF#19  -  []  34.85 -51.76 0 top
NOREF#20  -  []  21.8 9.8 0 top
NOREF#21  -  []  89.24 62.35 0 top
NOREF#22  -  []  55.3 8.18 0 top
NOREF#23  -  []  165 106.5 0 top
NOREF#24  -  []  132.66 108.98 180 bottom
NOREF#25  -  []  129.94 61.71 180 bottom
NOREF#26  -  []  213.44 104.58 180 bottom
NOREF#27  -  []  99.23 63.03 90 bottom
PBATT  LLTOP_ALLTOP C144LS-109A9-L 9P BATT P2  [ALLTO_C144LS-109A9-L_9P-T]  13.95 12.52 90 bottom
PC1  1000P_0402_50V7K  [C_0402]  16.44 116.84 270 bottom
